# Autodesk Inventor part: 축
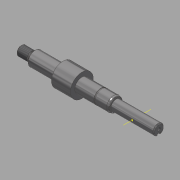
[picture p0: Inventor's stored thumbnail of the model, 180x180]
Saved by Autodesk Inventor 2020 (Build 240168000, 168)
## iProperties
Created: 2016-08
Part Number: 축
Material: 강철, 탄소
Document SubType Name: Modeling
Designer: mduedu
Density: 7.87 g/cm^3
Appearance: 반광택
Author: mduedu
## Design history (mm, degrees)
sketch "스케치1"
  geometry: L1 (-72.5, 0)-(72.5, 0); L2 (-72.5, 0)-(-72.5, 5); L3 (-72.5, 5)-(-58.5, 5); L4 (-58.5, 5)-(-58.5, 7.5); L5 (-58.5, 7.5)-(25.855, 7.5); L6 (27.5, 6.55)-(27.5, 5.5); L7 (27.5, 5.5)-(72.5, 5.5); L8 (72.5, 5.5)-(72.5, 0); L9 (27.5, 6.55)-(25.855, 7.5); 2 further points
  constraints: 18 end point, 5 parallel, 2 perpendicular, 1 coincident, 1 horizontal, 1 midpoint
  dimensions: "d0" = 145 distance of L1.start L1.end; "d2" = 14 distance of L2.end L3.end; "d4" = 10 diameter of L3 L1; "d5" = 15 diameter of L5 L1; "d6" = 11 diameter of L7 L1; "d63" = 45 distance between parallel lines of L6 L8; "d64" = 30 deg angle of L5 L9; "d65" = 13.1 diameter of L6.start L1
revolve "회전1" sketch "스케치1" stored, may be unused: angle "d7" = 90 deg
sketch "스케치2"
  geometry: L1 (-58.5, -5)-(-58.5, 5) reference; L2 (72.5, -5.5)-(72.5, 5.5) reference; L3 (-58.5, 0)-(72.5, 0); L4 (-60.5, 4.5)-(-60.5, 5); L5 (-60.5, 5)-(-58.5, 5); L6 (-58.5, 5)-(-58.5, 4.5); L7 (-60.5, 4.5)-(-58.5, 4.5); 1 further point
  constraints: 10 end point, 2 midpoint, 1 parallel, 1 perpendicular, 1 point on line
  dimensions: "d8" = 2 distance of L4.end L5.end; "d10" = 10 diameter of L5 L3; "d11" = 9 diameter of L7 L3
revolve "회전2" sketch "스케치2" stored, may be unused: angle "d12" = 90 deg
node "작업 평면1"
sketch "스케치3"
  geometry: C1 r 12 at (0, 0); 1 further point
  constraints: 1 centre point, 1 coincident
  dimensions: "d15" = 24 diameter of C1
extrude "돌출1" join sketch "스케치3" distance "d16" = 20; taper "d17" = 0 deg
sketch "스케치5"
  geometry: L1 (-72.5, -5)-(-72.5, 5) reference; L2 (72.5, -5.5)-(72.5, 5.5) reference; L3 (-72.5, 0)-(72.5, 0); L4 (-8.5, 7.5)-(25.855, 7.5) reference; L5 (12.65, 7.5)-(11.5, 7.5); L6 (11.5, 7.5)-(11.5, 7.15); L7 (11.5, 7.15)-(12.65, 7.15); L8 (12.65, 7.15)-(12.65, 7.5); L9 (-8.5, -12)-(-8.5, 12) reference; 1 further point
  constraints: 10 end point, 2 midpoint, 2 parallel, 1 horizontal, 1 perpendicular, 1 point on line
  dimensions: "d20" = 1.15 distance between parallel lines of L8 L6; "d21" = 14.3 diameter of L7 L3; "d82" = 20 distance between parallel lines of L9 L6
revolve "회전3" sketch "스케치5" stored, may be unused: angle "d22" = 90 deg
node "작업 평면3"
sketch "스케치6"
  geometry: L1 (-6.5, 2)-(-22.5, 2); L2 (-22.5, 2)-(-22.5, -2); L3 (-22.5, -2)-(-6.5, -2); L4 (-22.5, 5.5)-(-22.5, -5.5) reference; A1 r 2 centre (-6.5, 0) between (-6.5, -2) and (-6.5, 2); 2 further points
  constraints: 6 end point, 2 midpoint, 2 point on circle, 2 tangent, 1 centre point, 1 horizontal, 1 horizontal alignment, 1 parallel, 1 perpendicular
  dimensions: "d23" = 4 distance between parallel lines of L3 L1; "d62" = 18 dimension on A1 L2
extrude "돌출2" cut sketch "스케치6" distance "d25" = 2.5; taper "d26" = 0 deg
feature "스레드1" dims "d27" = 10, "d28" = 0
chamfer "모따기5" distance "d41" = 0.5; stored, may be unused: second distance "d42" = 2, angle "d43" = 45 deg
chamfer "모따기7" distance "d47" = 1; stored, may be unused: second distance "d48" = 2, angle "d49" = 45 deg
chamfer "모따기8" distance "d50" = 1; stored, may be unused: second distance "d51" = 2, angle "d52" = 45 deg
sketch "스케치8"
  geometry: 1 further point
hole "구멍1" sketch "스케치8" at (2, 3.5) diameter "d53" = 3.242; stored, may be unused: countersink angle "d57" = 90 deg, drill point angle "d59" = 120 deg; dims "d54" = 10, "d55" = 4, "d56" = 2, "d58" = 12
fillet "모깎기1" dims "d66" = 4, "d67" = 0.5
sketch "스케치10"
  geometry: L1 (-27.5, 5.5)-(-71.5, 5.5) reference; L2 (-51, 5.5)-(-49.5, 4); L3 (-49.5, 4)-(-49.5, 5.5); L4 (-72.5, -4.5)-(-72.5, 4.5) reference; 3 further points
  constraints: 4 end point, 1 midpoint, 1 perpendicular, 1 point on line
  dimensions: "d77" = 45 deg angle of L2 L3; "d78" = 3 diameter of L2.start L3; "d80" = 23 distance between parallel lines of L4 L3
revolve "회전4" sketch "스케치10" stored, may be unused: angle "d81" = 90 deg
node "작업점1"
node "작업축1"
node "솔리드1"
other parameters: "d13" = -44
